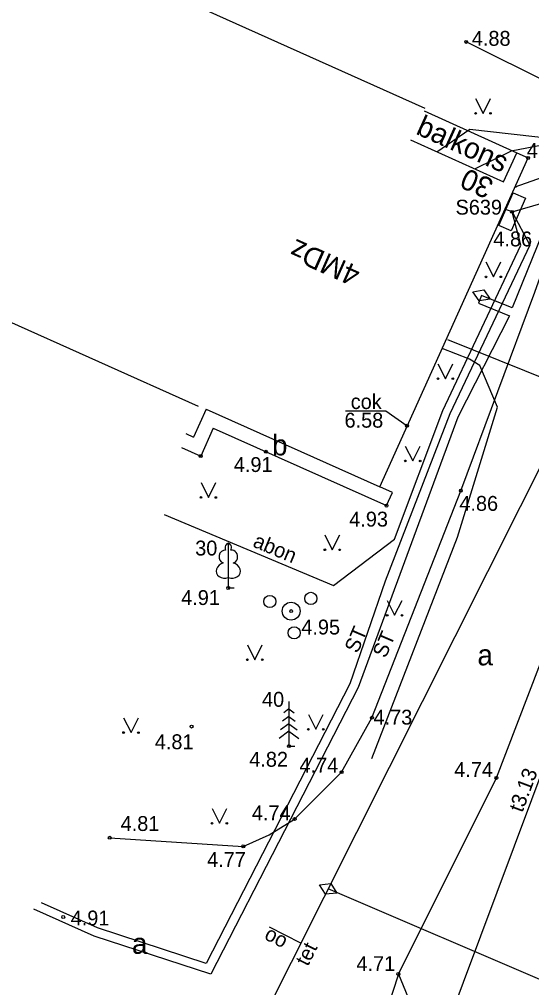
# Model space of a CAD drawing. Extents: x 484635 to 484808, y 278866 to 278977.
# Drawn here: x 484744.56 to 484761.78, y 278921.23 to 278953.76 of the extents above; entities that cross this region are included whole.
import ezdxf

# ---------------------------------------------------------------- set-up
doc = ezdxf.new("R2010")
doc.units = 0
for name, color, linetype in [('APGS_VADP_NEDR_####_#', 7, 'Continuous'), ('APGS_VADP_ZSPR_####_#', 7, 'Continuous'), ('BUVE_BALK_####_####_#', 7, 'Continuous'), ('BUVE_COKL_####_####_#', 7, 'Continuous'), ('BUVE_EKAS_####_####_#', 7, 'Continuous'), ('BUVE_EKAS_ADRS_TKST_#', 7, 'Continuous'), ('BUVE_EKAS_RAKS_TKST_#', 7, 'Continuous'), ('CELI_CAPM_####_####_#', 7, 'Continuous'), ('CELI_CMAL_####_####_#', 7, 'Continuous'), ('CELI_CSEG_####_TKST_#', 7, 'Continuous'), ('ELEK_ELEM_####_####_#', 7, 'Continuous'), ('ELEK_ELEM_####_TKST_#', 7, 'Continuous'), ('ELEK_VADP_ZSPR_####_#', 7, 'Continuous'), ('ELEK_VADP_ZSPR_TKST_#', 7, 'Continuous'), ('RELJ_AATZ_####_TKST_#', 7, 'Continuous'), ('RELJ_ELEM_####_####_#', 7, 'Continuous'), ('SAKK_ELEM_####_####_#', 7, 'Continuous'), ('SAKK_IZVK_####_TKST_#', 7, 'Continuous'), ('SAKK_KKAN_####_####_#', 7, 'Continuous'), ('SAKK_KKAN_####_####_I', 7, 'Continuous'), ('SAKK_KKAN_####_TKST_#', 7, 'Continuous'), ('SAKT_VADP_KABE_####_#', 7, 'Continuous'), ('SKAN_VADP_NEDR_####_#', 7, 'Continuous'), ('SKAN_VADP_NEDR_TKST_#', 7, 'Continuous'), ('TERT_DIAM_####_TKST_#', 7, 'Continuous'), ('TERT_ELEM_####_####_#', 7, 'Continuous'), ('UDTK_VADP_NEDR_####_#', 7, 'Continuous')]:
    doc.layers.add(name, color=color, linetype=linetype)

msp = doc.modelspace()

# ---------------------------------------------------------------- linework, layer by layer
at = {"layer": 'APGS_VADP_NEDR_####_#'}
msp.add_lwpolyline([(484756.41, 278928.919), (484759.29, 278936.357), (484760.63, 278940.723), (484760.041, 278942.127), (484759.693, 278942.339), (484758.77, 278942.693)], dxfattribs=at)
at = {"layer": 'APGS_VADP_ZSPR_####_#'}
msp.add_lwpolyline([(484758.95, 278942.999), (484764.131, 278940.921), (484767.852, 278949.207), (484766.539, 278950.935), (484767.13, 278953.024), (484770.675, 278961.156)], dxfattribs=at)
at = {"layer": 'BUVE_BALK_####_####_#'}
msp.add_line((484758.164, 278950.678), (484761.279, 278949.272), dxfattribs=at)
at = {"layer": 'BUVE_COKL_####_####_#'}
for p, q in [((484755.529, 278940.606), (484756.884, 278940.606)), ((484756.884, 278940.606), (484757.594, 278940.105))]:
    msp.add_line(p, q, dxfattribs=at)
at = {"layer": 'BUVE_EKAS_####_####_#'}
for p, q in [((484757.708, 278949.71), (484760.839, 278948.296)), ((484760.839, 278948.296), (484761.279, 278949.272)), ((484761.279, 278949.272), (484761.662, 278949.099)), ((484756.678, 278938.055), (484761.662, 278949.099)), ((484750.835, 278940.661), (484750.415, 278939.72)), ((484750.835, 278940.661), (484756.678, 278938.055)), ((484750.151, 278939.838), (484750.415, 278939.72))]:
    msp.add_line(p, q, dxfattribs=at)
for points in [[(484758.206, 278950.764), (484732.124, 278962.447), (484730.484, 278958.706)], [(484725.298, 278947.487), (484727.109, 278951.269), (484750.575, 278940.758)]]:
    msp.add_lwpolyline(points, dxfattribs=at)
at = {"layer": 'CELI_CAPM_####_####_#'}
msp.add_lwpolyline([(484747.598, 278926.26), (484752.085, 278925.972), (484752.96, 278926.364), (484753.814, 278926.888), (484755.393, 278928.465), (484756.413, 278930.294), (484759.401, 278937.921), (484761.893, 278944.594), (484763.269, 278948.465), (484763.435, 278949.603), (484763.231, 278950.715), (484762.525, 278951.531), (484759.58, 278952.998)], dxfattribs=at)
at = {"layer": 'CELI_CMAL_####_####_#'}
for p, q in [((484751.074, 278940.019), (484750.658, 278939.086)), ((484751.074, 278940.019), (484756.902, 278937.42)), ((484750.005, 278939.377), (484750.658, 278939.086)), ((484757.103, 278937.863), (484756.678, 278938.055)), ((484756.902, 278937.42), (484757.103, 278937.863))]:
    msp.add_line(p, q, dxfattribs=at)
for points in [[(484757.301, 278921.684), (484760.599, 278928.271), (484763.134, 278934.868), (484765.628, 278941.251)], [(484757.301, 278921.684), (484755.548, 278916.308), (484754.577, 278916.086)], [(484757.301, 278921.684), (484759.431, 278916.509), (484764.605, 278914.081)]]:
    msp.add_lwpolyline(points, dxfattribs=at)
at = {"layer": 'ELEK_ELEM_####_####_#'}
for points in [[(484761.573, 278947.748), (484761.089, 278946.65), (484760.677, 278946.832), (484761.161, 278947.93)], [(484759.801, 278944.602), (484760.173, 278944.664), (484760.392, 278944.358), (484760.02, 278944.295)]]:
    msp.add_lwpolyline(points, close=True, dxfattribs=at)
at = {"layer": 'ELEK_VADP_ZSPR_####_#'}
for points in [[(484761.125, 278947.29), (484769.574, 278949.742), (484773.55, 278959.756)], [(484773.782, 278959.529), (484769.799, 278949.495), (484762.476, 278947.375), (484761.122, 278944.061), (484760.097, 278944.48), (484759.99, 278944.218), (484761.033, 278943.792), (484759.305, 278940.39), (484755.946, 278931.315), (484750.993, 278921.676), (484747.073, 278922.96), (484745.044, 278923.863)], [(484761.125, 278947.29), (484761.717, 278946.166), (484759.029, 278940.508), (484756.852, 278934.879), (484755.669, 278931.433), (484750.844, 278922.04), (484747.181, 278923.24), (484745.3, 278924.077)], [(484749.429, 278937.123), (484755.122, 278934.739), (484757.166, 278936.288), (484758.801, 278940.616), (484761.416, 278946.173), (484761.125, 278947.29)], [(484761.125, 278947.29), (484760.883, 278947.377)]]:
    msp.add_lwpolyline(points, dxfattribs=at)
at = {"layer": 'RELJ_ELEM_####_####_#'}
for centre in [(484759.58, 278952.998), (484761.662, 278949.099), (484761.125, 278947.29), (484757.594, 278940.105), (484750.658, 278939.086), (484752.846, 278939.228), (484759.401, 278937.921), (484756.902, 278937.42), (484751.583, 278934.654), (484753.697, 278933.875), (484756.413, 278930.294), (484750.347, 278929.999), (484753.621, 278929.34), (484755.393, 278928.465), (484760.599, 278928.271), (484753.814, 278926.888), (484747.598, 278926.26), (484752.085, 278925.972), (484746.035, 278923.599), (484757.301, 278921.684)]:
    msp.add_circle(centre, 0.05, dxfattribs=at)
at = {"layer": 'SAKK_ELEM_####_####_#'}
msp.add_lwpolyline([(484754.654, 278924.684), (484755.03, 278924.721), (484755.227, 278924.399), (484754.852, 278924.362)], close=True, dxfattribs=at)
at = {"layer": 'SAKK_IZVK_####_TKST_#'}
msp.add_line((484754.026, 278922.724), (484752.972, 278923.254), dxfattribs=at)
at = {"layer": 'SAKK_KKAN_####_####_#'}
for points in [[(484747.103, 278908.959), (484768.008, 278950.519)], [(484768.008, 278950.519), (484761.221, 278948.116), (484761.269, 278948.133)]]:
    msp.add_lwpolyline(points, dxfattribs=at)
at = {"layer": 'SAKK_KKAN_####_####_I'}
msp.add_line((484766.75, 278919.495), (484754.941, 278924.541), dxfattribs=at)
at = {"layer": 'SAKT_VADP_KABE_####_#'}
msp.add_lwpolyline([(484768.008, 278950.519), (484765.073, 278950.088), (484761.098, 278949.331), (484759.878, 278948.735)], dxfattribs=at)
at = {"layer": 'SKAN_VADP_NEDR_####_#'}
msp.add_lwpolyline([(484751.85, 278901.026), (484758.323, 278918.301), (484762.372, 278929.106)], dxfattribs=at)
at = {"layer": 'TERT_ELEM_####_####_#'}
for p, q in [((484759.899, 278951.099), (484760.149, 278950.599)), ((484760.149, 278950.599), (484760.399, 278951.099)), ((484760.245, 278945.606), (484760.495, 278945.106)), ((484760.495, 278945.106), (484760.745, 278945.606)), ((484758.632, 278942.184), (484758.882, 278941.684)), ((484758.882, 278941.684), (484759.132, 278942.184)), ((484757.535, 278939.422), (484757.785, 278938.922)), ((484757.785, 278938.922), (484758.035, 278939.422)), ((484750.667, 278938.193), (484750.917, 278937.693)), ((484750.917, 278937.693), (484751.167, 278938.193)), ((484754.831, 278936.437), (484755.081, 278935.937)), ((484755.081, 278935.937), (484755.331, 278936.437)), ((484751.583, 278935.001), (484751.583, 278934.654)), ((484751.583, 278934.654), (484751.783, 278934.654)), ((484756.925, 278934.235), (484757.175, 278933.735)), ((484757.175, 278933.735), (484757.425, 278934.235)), ((484752.224, 278932.742), (484752.474, 278932.242)), ((484752.474, 278932.242), (484752.724, 278932.742)), ((484753.621, 278930.84), (484753.621, 278929.34)), ((484753.621, 278930.34), (484753.405, 278930.182)), ((484753.621, 278930.59), (484753.445, 278930.462)), ((484753.621, 278930.59), (484753.795, 278930.462)), ((484753.621, 278930.34), (484753.837, 278930.182)), ((484754.276, 278930.406), (484754.526, 278929.906)), ((484754.526, 278929.906), (484754.776, 278930.406)), ((484748.063, 278930.296), (484748.313, 278929.796)), ((484748.313, 278929.796), (484748.563, 278930.296)), ((484753.621, 278930.09), (484753.343, 278929.886)), ((484753.621, 278930.09), (484753.899, 278929.886)), ((484753.621, 278929.84), (484753.289, 278929.596)), ((484753.621, 278929.84), (484753.955, 278929.596)), ((484753.621, 278929.34), (484753.821, 278929.34)), ((484751.037, 278927.247), (484751.287, 278926.747)), ((484751.287, 278926.747), (484751.537, 278927.247))]:
    msp.add_line(p, q, dxfattribs=at)
for points in [[(484751.583, 278936.154), (484751.583, 278935.001)], [(484751.673, 278935.921), (484751.672, 278935.922)]]:
    msp.add_lwpolyline(points, dxfattribs=at)
for centre, radius in [((484759.898, 278950.598), 0.028), ((484760.398, 278950.598), 0.0263), ((484760.245, 278945.105), 0.028), ((484760.745, 278945.105), 0.0263), ((484758.632, 278941.683), 0.028), ((484759.132, 278941.683), 0.0263), ((484757.535, 278938.922), 0.028), ((484758.035, 278938.922), 0.0263), ((484750.666, 278937.693), 0.028), ((484751.166, 278937.693), 0.0263), ((484754.831, 278935.936), 0.028), ((484755.331, 278935.936), 0.0263), ((484752.982, 278934.199), 0.204), ((484754.358, 278934.3), 0.207), ((484753.696, 278933.875), 0.301), ((484756.925, 278933.734), 0.028), ((484757.425, 278933.734), 0.0263), ((484753.8, 278933.147), 0.205), ((484752.224, 278932.241), 0.028), ((484752.724, 278932.241), 0.0263), ((484748.063, 278929.795), 0.028), ((484748.563, 278929.795), 0.0263), ((484754.275, 278929.906), 0.028), ((484754.775, 278929.906), 0.0263), ((484751.036, 278926.747), 0.028), ((484751.536, 278926.747), 0.0263)]:
    msp.add_circle(centre, radius, dxfattribs=at)
for centre, major_axis, ratio, start_param, end_param in [((484751.455, 278935.709), (-0.039, -0.212), 0.861323, 3.141593, 6.283185), ((484751.584, 278936.004), (0, -0.15), 0.707107, 3.14537, 5.287485), ((484751.583, 278936.004), (0, -0.15), 0.707107, 0.995701, 3.137816), ((484751.711, 278935.709), (0.039, -0.212), 0.861323, 0, 3.141593), ((484751.494, 278935.247), (0.307, 0.095), 0.814445, 1.570796, 4.752015), ((484751.673, 278935.247), (-0.307, 0.095), 0.814445, 1.531171, 4.712389)]:
    msp.add_ellipse(centre, major_axis=major_axis, ratio=ratio, start_param=start_param, end_param=end_param, dxfattribs=at)
at = {"layer": 'UDTK_VADP_NEDR_####_#'}
msp.add_lwpolyline([(484758.595, 278949.309), (484759.709, 278950.067), (484773.313, 278948.534)], dxfattribs=at)

# ---------------------------------------------------------------- texts
at = {"layer": 'BUVE_COKL_####_####_#'}
for s, p in [('cok', (484755.7, 278940.665)), ('6.58', (484755.491, 278940.039))]:
    msp.add_text(s, height=0.5, dxfattribs=at).set_placement(p)
at = {"layer": 'BUVE_EKAS_ADRS_TKST_#'}
msp.add_text('30', height=0.7, rotation=155.7096, dxfattribs=at).set_placement((484760.554, 278948.344))
at = {"layer": 'BUVE_EKAS_RAKS_TKST_#'}
for s, rotation, p in [('balkons', 335.7096, (484757.855, 278949.92)), ('4MDz', 155.9635, (484756.079, 278945.402))]:
    msp.add_text(s, height=0.7, rotation=rotation, dxfattribs=at).set_placement(p)
at = {"layer": 'CELI_CSEG_####_TKST_#'}
for s, p in [('b', (484753.054, 278939.105)), ('a', (484759.959, 278932.054)), ('a', (484748.345, 278922.362))]:
    msp.add_text(s, height=0.7, dxfattribs=at).set_placement(p)
at = {"layer": 'ELEK_ELEM_####_TKST_#'}
msp.add_text('S639', height=0.5, dxfattribs=at).set_placement((484759.223, 278947.196))
at = {"layer": 'ELEK_VADP_ZSPR_TKST_#'}
for s, rotation, p in [('abon', 337.2809, (484752.377, 278936.051)), ('ST', 66.6432, (484755.931, 278932.433)), ('ST', 66.9166, (484756.875, 278932.271))]:
    msp.add_text(s, height=0.5, rotation=rotation, dxfattribs=at).set_placement(p)
at = {"layer": 'RELJ_AATZ_####_TKST_#'}
for s, p in [('4.88', (484759.771, 278952.868)), ('4.93', (484761.62, 278949.103)), ('4.86', (484760.495, 278946.129)), ('4.91', (484751.77, 278938.55)), ('4.86', (484759.352, 278937.245)), ('4.93', (484755.65, 278936.716)), ('4.91', (484750, 278934.081)), ('4.95', (484754.039, 278933.09)), ('4.73', (484756.466, 278930.063)), ('4.81', (484749.113, 278929.237)), ('4.82', (484752.289, 278928.647)), ('4.74', (484753.978, 278928.447)), ('4.74', (484759.18, 278928.302)), ('4.74', (484752.376, 278926.85)), ('4.81', (484747.965, 278926.49)), ('4.77', (484750.872, 278925.283)), ('4.91', (484746.285, 278923.315)), ('4.71', (484755.892, 278921.783))]:
    msp.add_text(s, height=0.5, dxfattribs=at).set_placement(p)
at = {"layer": 'SAKK_IZVK_####_TKST_#'}
msp.add_text('oo', height=0.5, rotation=333.2965, dxfattribs=at).set_placement((484752.76, 278922.874))
at = {"layer": 'SAKK_KKAN_####_TKST_#'}
msp.add_text('tet', height=0.5, rotation=63.2965, dxfattribs=at).set_placement((484754.258, 278921.918))
at = {"layer": 'SKAN_VADP_NEDR_TKST_#'}
msp.add_text('t3.13', height=0.5, rotation=69.4583, dxfattribs=at).set_placement((484761.469, 278927.085))
at = {"layer": 'TERT_DIAM_####_TKST_#'}
for s, p in [('30', (484750.471, 278935.744)), ('40', (484752.717, 278930.662))]:
    msp.add_text(s, height=0.5, dxfattribs=at).set_placement(p)

doc.saveas('drawing.dxf')
